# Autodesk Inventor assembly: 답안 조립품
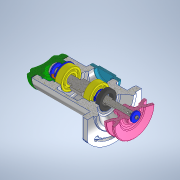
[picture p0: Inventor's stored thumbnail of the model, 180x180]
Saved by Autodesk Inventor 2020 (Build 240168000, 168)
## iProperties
Created: 2022-05
Part Number: 답안 조립품
Document SubType Name: Assembly
Designer: Student
Author: Student
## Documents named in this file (18)
- C:\Users\Student\Desktop\720506V1024\답안 조립품.iam
- C:\Users\Student\Desktop\720506V1024\본체.ipt
- C:\Users\Student\Desktop\720506V1024\사이드 커버.ipt
- 사이드 커버.ipt
- C:\Users\Student\Desktop\720506V1024\베어링 6202.ipt
- C:\Users\Student\Desktop\720506V1024\축.ipt
- C:\Users\Student\Desktop\720506V1024\멈춤링 35 x 1.6.ipt
- C:\Users\Student\Desktop\720506V1024\멈춤링 15 x 1.ipt
- C:\Users\Student\Desktop\720506V1024\개스킷.ipt
- C:\Users\Student\Desktop\720506V1024\탑 커버.ipt
- C:\Users\Student\Desktop\720506V1024\키 4 x 4.ipt
- C:\Users\Student\Desktop\720506V1024\오일 실 15 x 30 x 7.ipt
- C:\Users\Student\Desktop\720506V1024\부시2.ipt
- C:\Users\Student\Desktop\720506V1024\와셔 10 x 21.ipt
- C:\Users\Student\Desktop\720506V1024\너트 M10.ipt
- C:\Users\Student\Desktop\720506V1024\V-벨트풀리.ipt
- C:\Users\Student\Desktop\720506V1024\와셔 4 x 16.ipt
- C:\Users\Student\Desktop\720506V1024\십자볼트 M3 x 10.ipt
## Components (2 placed, 2 different names)
1. 개스킷:1
2. V-벨트풀리:1
